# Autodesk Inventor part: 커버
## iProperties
Created: 2013-05
Part Number: 커버
Document SubType Name: Modeling
Designer: SeoGD™
Density: 1 g/cm^3
Mass: 89.4779 g
Surface Area: 390.137 cm^2
Volume: 89.4779 cm^3
Author: SeoGD™
